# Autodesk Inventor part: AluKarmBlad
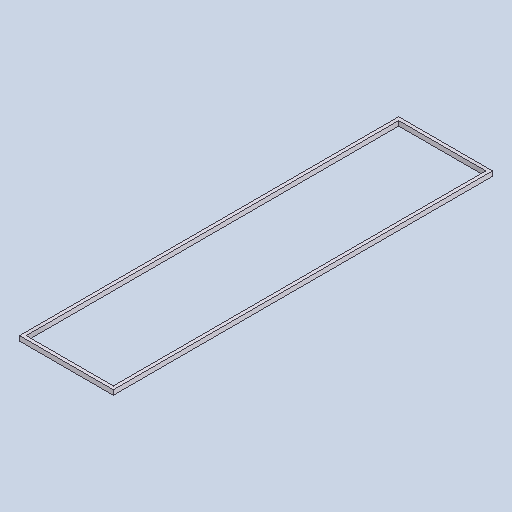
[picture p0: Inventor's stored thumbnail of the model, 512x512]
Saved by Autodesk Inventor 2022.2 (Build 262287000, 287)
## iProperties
Created: 2019-06
Part Number: AluKarmBlad
Material: Aluminum 6061, Welded
Document SubType Name: Modeling
Designer: cl
Density: 2.7 g/cm^3
Appearance: Weld - Aluminum
Author: cl
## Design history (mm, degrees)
sketch "Sketch3"
  geometry: L1 (0, 0)-(987.5, 0); L2 (987.5, 0)-(987.5, -3991); L3 (987.5, -3991)-(0, -3991); L4 (0, -3991)-(0, 0); L5 (952.5, -3956)-(952.5, -35); L6 (952.5, -35)-(35, -35); L7 (35, -35)-(35, -3956); L8 (35, -3956)-(952.5, -3956)
  constraints: 16 end point, 4 parallel, 2 perpendicular, 1 horizontal, 3 other
  dimensions: "d31" = 3991 distance of L1.end L2.end (derived); "d32" = 987.5 distance between parallel lines of L4 L2 (derived); "d33" = 35 distance between parallel lines of L2 L5
extrude "Extrusion3" new body sketch "Sketch3" distance "d34" = 50; taper "d35" = 0 deg
body "Solid3"
other parameters: "BladBredd" = 987.5
